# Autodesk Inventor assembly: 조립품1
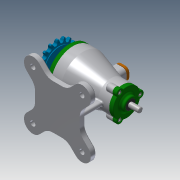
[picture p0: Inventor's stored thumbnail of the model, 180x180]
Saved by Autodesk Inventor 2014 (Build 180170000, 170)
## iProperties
Created: 2018-03
Part Number: 조립품1
Document SubType Name: Assembly
Designer: net
Author: net
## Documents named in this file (15)
- C:\Users\net\Desktop\480307V1021\조립품1.iam
- C:\Users\net\Desktop\480307V1021\본체.ipt
- C:\Users\net\Desktop\480307V1021\베어링-6200.ipt
- C:\Users\net\Desktop\480307V1021\뒤커버.ipt
- C:\Users\net\Desktop\480307V1021\오일 실 10 20 7.ipt
- C:\Users\net\Desktop\480307V1021\축.ipt
- C:\Users\net\Desktop\480307V1021\볼트 M4 x 12.ipt
- 볼트 M4 x 12.ipt
- C:\Users\net\Desktop\480307V1021\앞커버.ipt
- C:\Users\net\Desktop\480307V1021\베어링-6203.ipt
- C:\Users\net\Desktop\480307V1021\마개.ipt
- C:\Users\net\Desktop\480307V1021\오일 실 17 30 8.ipt
- C:\Users\net\Desktop\480307V1021\스프로킷.ipt
- C:\Users\net\Desktop\480307V1021\키 5 x 5.ipt
- 키 5 x 5.ipt
